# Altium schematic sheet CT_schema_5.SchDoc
size 257 x 245 mm
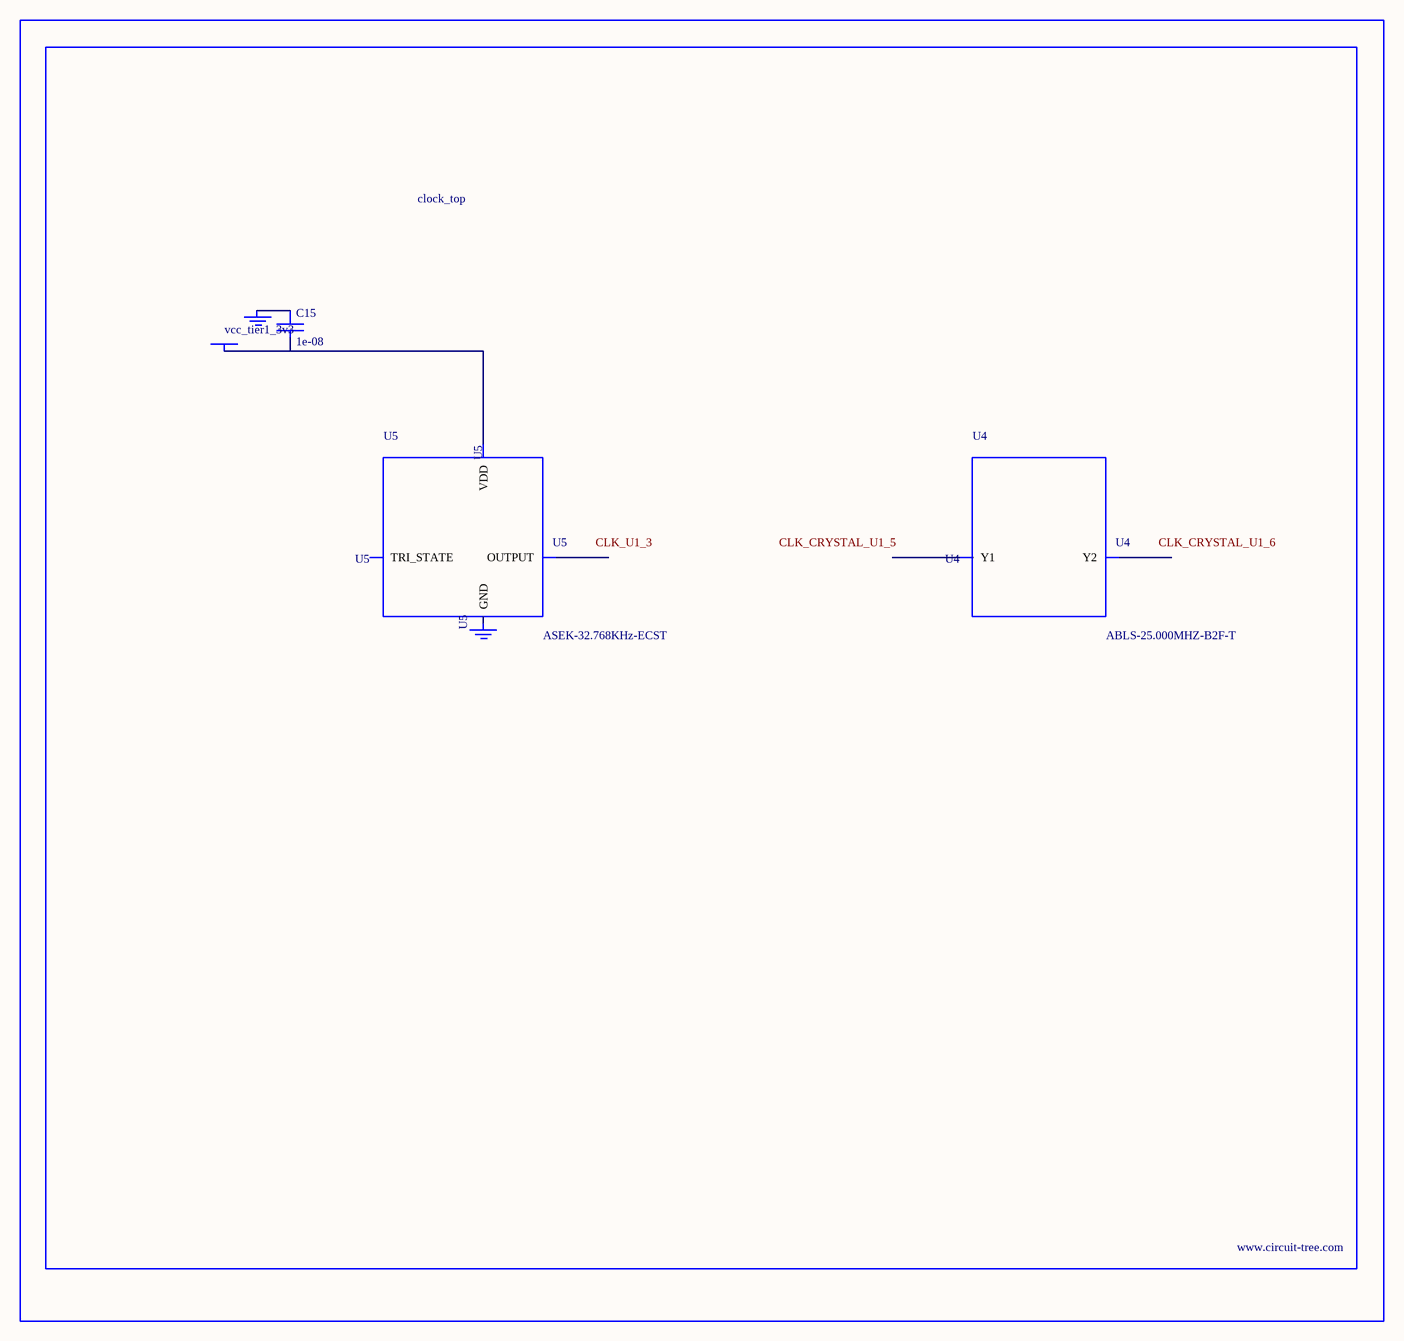
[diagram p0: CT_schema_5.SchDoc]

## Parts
BORDER4  (no value)
C15  1e-08  [C0402]
GND_INSTANCE_4_0  (no value)
GND_INSTANCE_4_1  (no value)
POWER_INSTANCE_4_0  vcc_tier1_3v3
U4  ABLS-25.000MHZ-B2F-T  [ABLS-25.000MHZ-B2F-T]
U5  ASEK-32.768KHz-ECST  [ASEK]

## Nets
NetC15_1: C15.1 GND_INSTANCE_4_0.0(GND)
NetC15_2: C15.2 POWER_INSTANCE_4_0.0(PWR) U5.4(VDD)

Not connected (* = marked no-connect by the designer): GND_INSTANCE_4_1 0(GND); U4 1(Y1) 2(Y2); U5 1(TRI_STATE) 2(GND) 3(OUTPUT)

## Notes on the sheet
- Labels drawn without touching a wire or pin: CLK_CRYSTAL_U1_5, CLK_CRYSTAL_U1_6, CLK_U1_3

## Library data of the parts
BORDER4 = BORDER_PAGE4
C15 = C0402C103K3RAC
GND_INSTANCE_4_0 GND_INSTANCE_4_1 = GND
POWER_INSTANCE_4_0 = PWR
